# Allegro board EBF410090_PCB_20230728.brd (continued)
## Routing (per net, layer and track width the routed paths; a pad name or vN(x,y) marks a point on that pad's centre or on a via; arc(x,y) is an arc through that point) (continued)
VCC3V3_SD: length 145.4
  TOP w0.305: v1(17.73,30.2) 17.65,30.28 17.65,51.56 17.76,51.67 J30.244 17.78,54.09 17.78,58.93 18.01,59.16 J30.243
  ART03 w0.381: v1(109.65,25.41) 109.83,25.6 109.83,28.24 109.45,28.62 85.17,28.62 83.85,29.95 74.14,29.95 72.19,27.99 18.49,27.99 17.73,28.75 v1(17.73,30.2)
  BOTTOM w0.305: C54.1 114.42,26.39 ; 114.42,26.39 114.42,26.28 113.56,25.42 109.66,25.42 v1(109.65,25.41) ; 114.42,26.39 115.08,25.73 116.38,25.73 116.96,26.31 116.96,26.39 ; C73.1 116.96,26.39 ; 116.96,26.39 117.57,25.78 118.89,25.78 119.5,26.38 C74.1 120.35,25.56 J9.4
VCC3V3_SYS: length 11.2
  TOP w0.305: U31.5 v1(120.83,66.49) ; U32.5 v1(120.83,44.39)
  ART04 w0.305: v1(12.69,31.2) 12.7,31.2
  BOTTOM w0.305: U35.5 v1(71.56,26.52) ; R4.1 C8.1 7.23,50.43 7.7,49.96 7.7,47.92 C15.1
  vias: v1(5.46,45.85) v1(6.48,45.85) v1(7.49,45.85) v1(11.69,35.01) v1(11.69,31.2) v1(12.69,35.01) v1(70.56,26.52) v1(119.83,66.49) v1(119.83,44.39)
VCC5V0_SYS: length 16.2
  TOP w0.305: U33.5 v1(120.83,58.36) ; v1(13.26,52.32) 12.13,53.46 8.2,53.46 8.07,53.33 R16.1 ; U34.5 v1(120.83,36.26) ; U29.5 v1(120.83,61.66) ; U30.5 v1(120.83,39.56)
  ART04 w0.305: v1(120.83,61.66) v1(120.83,58.36)
  BOTTOM w0.305: C51.1 14.11,53.74 C20.1 R11.1
  vias: v1(13.26,51.32) v1(13.26,50.32) v1(14.26,52.32) v1(14.26,51.32) v1(14.26,50.32) v1(19.92,52.58) v1(19.89,51.69) v1(119.83,61.66) v1(119.83,58.36) v1(119.83,39.56) v1(119.83,36.26)
VCC5V0_SYS_2: length 16
  ART04 w0.508: v1(121.79,85.66) v1(121.79,84.41)
  BOTTOM w0.305: U21.5 v1(121.79,85.66) ; C36.1 13.85,69.05 13.26,69.65 7.7,69.65 7.37,69.97 C29.1 R20.1
  BOTTOM w0.381: R10.1 25.91,61.18 v1(25.51,60.78)
  vias: v1(11.69,38.82) v1(12.69,38.82) v1(15.38,69.23) v1(15.38,68.23) v1(16.38,69.29) v1(16.38,68.23) v1(106.92,84.71) v1(107.92,84.71)
VCC5V0_USB20_HOST: length 15.2
  BOTTOM w0.508: J17.1 J17.7 116.15,82.35 115.57,82.93 C113.1 C112.1 C117.1 C116.1 118.68,85.66 U21.1
VCC5V0_USB30_HOST: length 18.8
  TOP w0.508: J15.10 97.62,77.17 98.81,78.36 98.81,79.71 98.14,80.37 J15.1
  BOTTOM w0.508: J15.1 97.92,81.15 97.92,85.99 98.42,86.49 C123.1 C122.1 103.57,85.66 U24.1
VCC_1V8: length 109.1
  TOP w0.305: J30.245 17.51,59.55 17.26,59.3 J30.246 17.26,52.19 17.02,51.94 v1(17.02,38.48)
  ART04 w0.381: v1(33.76,37.41) 48.95,37.41 50.29,36.07 62.43,36.07 63.09,36.73 77.98,36.73 78.98,37.73 78.98,45.6 v1(78.24,46.35)
  BOTTOM w0.203: R38.1 16.71,34.68 16.46,34.93 16.46,37.34 16.83,37.71 C52.1
  BOTTOM w0.305: v1(17.02,38.48) C52.1 C57.1 C58.1 20.88,37.71 U8.8 22.35,37.72 23.37,38.73 30.63,38.73 31.24,38.12 R37.1 33.46,36.19 33.76,36.49 v1(33.76,37.41) ; L7.2 77.47,48.17 C105.1 v1(78.24,46.35)
VCC_12V: length 23.9
  TOP w0.305: C165.1 R196.1 128.49,26.67 v1(128.74,26.93) ; v1(8.43,58.16) 8.26,57.99 R14.1 ; R23.1 v1(2.16,63.78) ; R7.1 7.24,59.89
  BOTTOM w0.305: C38.1 v1(21.58,43.73) R27.1 ; C22.1 v1(8.43,58.16)
  BOTTOM w0.381: v1(25.51,59.78) 27.51,59.78 27.81,60.09 27.81,60.96 27.43,61.34 R9.1
  BOTTOM w0.508: v1(128.74,26.93) 125.06,26.93 124.45,27.54 v1(124.45,31.7)
  vias: v1(1.84,61.01) v1(1.84,59.99) v1(2.85,61.01) v1(2.85,59.99) v1(9.09,63.01) v1(9.09,62.01) v1(9.09,61.01) v1(10.09,63.01) v1(10.09,62.01) v1(10.09,61.01) v1(16.26,44.94) v1(16.26,43.94) v1(97.52,41.25) v1(98.52,41.25) v1(99.52,41.25) v1(124.45,32.7)
VCC_RTC: length 26.8
  TOP w0.305: J30.248 16.76,59.74 17.01,59.99 J30.247 17.01,63.37 18.21,64.57 18.21,73.33 17.88,73.66 15.95,73.66 v1(15.64,73.97)
  BOTTOM w0.305: R51.2 15.33,75.32 15.64,75.01 v1(15.64,73.97)
VCCA_1V8: length 57.1
  TOP w0.305: J30.239 19.01,58.51 18.76,58.26 J30.240 18.76,52.15 19.1,51.81 19.1,41.27 v1(20.01,40.36) ; C53.1 v1(27.56,40.66) ; v1(5.69,41.63) 6.25,42.19 6.25,44.04 4.83,45.46 4.83,46.49 R239.2 ; R35.1 v1(27.56,44.16)
  ART03 w0.381: v1(5.69,41.63) 18.74,41.63 v1(20.01,40.36) 20.88,41.22 27,41.22 v1(27.56,40.66)
  BOTTOM w0.305: v1(27.56,40.66) 27,41.22 27,43.6 v1(27.56,44.16)
VCCIO_ACODEC: length 36.5
  TOP w0.305: R215.1 36.2,66.67 C186.1 v1(36.2,68.96) ; J30.242 18.26,58.57 18.51,58.82 J30.241 18.51,63.72 19.05,64.26 19.05,66.17 19.94,67.05 19.94,68.53 20.24,68.83 31.89,68.83 v1(32.51,68.21)
  BOTTOM w0.254: 32.51,68.97 v1(32.51,68.21)
  BOTTOM w0.305: v1(36.2,68.96) 35.05,70.11 R217.1 C191.1 32.51,68.97 C55.1
VDD_3V3: length 101.3
  TOP w0.305: LED3.2 LED2.2 LED1.2 ; Q7.2 91.94,33.24 C109.1 R127.1 91.95,31.35 92.61,30.7 92.61,28.11 v1(92.91,27.81) ; v1(125.43,68.83) R168.1 R164.1 ; v1(125.43,46.73) R170.1 R166.1
  TOP w0.381: LED1.2 v1(128.65,14.47)
  TOP w0.762: C431.1 88.01,12.66 J34.1
  PWR05 w0.508: 112.01,9.94 J36.1 ; J36.1 111.28,10.67 ; J36.1 112.74,10.67 ; J36.1 112.01,11.4 ; J35.1 100.74,10.67 ; J35.1 99.28,10.67 ; J35.1 100.01,11.4 ; J35.1 100.01,9.94 ; J34.1 88.01,11.4 ; J34.1 88.74,10.67 ; J34.1 88.01,9.94 ; J34.1 87.28,10.67 ; J32.1 76.01,11.4 ; J32.1 76.74,10.67 ; J32.1 75.28,10.67 ; J32.1 76.01,9.94
  BOTTOM w0.305: C5.1 7.74,31.88 C62.1 7.9,30.7 U10.5 ; v1(73.28,68.2) 72.76,68.71 R159.1 ; L5.2 73.44,35.69 C90.1 v1(74.42,34.92) 73.33,33.83 69.27,33.83 68.76,33.32 68.76,31.99 68.15,31.38 C75.1 U14.8 ; v1(54.23,31.38) C76.1 U15.8 ; v1(7.87,19.43) C59.1 9.45,18.66 9.76,18.96 9.76,19.74 9.45,20.04 U9.5 ; L6.2 56.23,38.23 C94.1 48.92,38.23 48.62,37.93 48.62,32.45 49.23,31.84 49.69,31.84 v1(49.69,31.85) 49.69,31.84 D20.2 ; v1(83.31,68.2) 83.31,68.32 R156.1 ; R39.1 v1(6.48,16.89) ; U13.16 40.25,31.37 C69.1 v1(41.01,31.38) ; R69.1 v1(68.51,20.71) ; R44.1 v1(127.76,11.17) ; 5.07,31.63 4.94,31.51 R42.1 ; C6.1 v1(5.69,32.01) ; v1(29.08,32.38) R52.1 R53.1 R55.1 R54.1 ; v1(128.65,79.12) C127.1 127.75,80.11 R152.1 ; R70.1 v1(54.36,20.71) ; R68.1 v1(48.82,20.71) ; D19.2 v1(63.78,31.88) ; D6.2 14.33,74.13 14.64,73.82 v1(14.64,72.97) ; R157.1 77.72,68.71 v1(78.23,68.2) ; R67.1 v1(62.87,20.71)
  BOTTOM w0.381: R47.2 v1(122.05,13.21)
  vias: v1(4.69,32.01) v1(14.64,71.97)
VDD_5V: length 33.8
  TOP w0.305: Q9.1 84.18,68.38 84.18,66.5 83.74,66.06 79.02,66.06 77.95,65 70.43,65 69.47,64.03 59.49,64.03 D27.2
  ART03 w0.305: v1(19.88,47.1) v1(19.88,48.1) ; v1(33.86,41.13) v1(33.86,42.13)
  ART04 w0.305: v1(33.86,41.13) v1(33.86,42.13)
  vias: v1(55.47,69.2) v1(56.47,69.2)
B_DM1: length 27.1
  BOTTOM w0.158: J15.11 93.91,77.17 92.82,76.07 92.82,75.04 91.76,73.98 85.78,73.98 84.6,75.16 84.6,77.08 84.96,77.44 84.96,78.1 85.83,78.97 86.67,78.97 90.76,83.07 90.76,83.84 90.69,83.91 U18.5 U18.6 90.69,85.97 R130.1
B_DM2: length 7.8
  BOTTOM w0.158: J17.8 112.83,79.31 112.83,80.97 112.08,81.72 112.08,82.44 112.15,82.51 U20.4 U20.7 112.15,85.6 R139.1
B_DM3: length 13
  BOTTOM w0.158: J17.2 112.83,76.31 112.83,76.53 113.01,76.71 114.25,76.71 115.09,77.55 115.09,80.62 113.58,82.13 113.58,82.44 113.65,82.51 U20.1 U20.10 113.65,85.08 R132.1
B_DP1: length 26.2
  BOTTOM w0.158: J15.12 92.46,76.99 92.46,75.19 91.61,74.34 91.16,74.34 arc(91.03,74.4) 90.98,74.52 arc(90.93,74.65) 90.8,74.7 90.53,74.7 arc(90.4,74.65) 90.35,74.52 arc(90.3,74.4) 90.17,74.34 89.89,74.34 arc(89.77,74.4) 89.72,74.52 arc(89.66,74.65) 89.54,74.7 89.26,74.7 arc(89.14,74.65) 89.08,74.52 arc(89.03,74.4) 88.91,74.34 88.63,74.34 arc(88.5,74.4) 88.45,74.52 arc(88.4,74.65) 88.27,74.7 87.99,74.7 arc(87.87,74.65) 87.82,74.52 arc(87.77,74.4) 87.64,74.34 87.36,74.34 arc(87.24,74.4) 87.18,74.52 arc(87.13,74.65) 87.01,74.7 86.73,74.7 arc(86.6,74.65) 86.55,74.52 arc(86.5,74.4) 86.37,74.34 85.93,74.34 84.96,75.31 84.96,76.93 85.32,77.29 85.32,77.95 85.98,78.61 86.82,78.61 91.12,82.92 91.12,83.84 91.19,83.91 U18.4 U18.7 91.19,85.24 R131.1
B_DP2: length 8
  BOTTOM w0.158: J17.9 112.47,79.31 112.47,80.82 111.72,81.57 111.72,82.44 111.65,82.51 U20.5 U20.6 111.65,85.08 R140.1
B_DP3: length 12.8
  BOTTOM w0.158: R133.1 113.15,85.6 U20.9 U20.2 113.15,82.51 113.22,82.44 113.22,81.98 114.73,80.47 114.73,77.7 114.1,77.07 112.86,77.07 112.47,76.68 112.47,76.31 J17.3
BD_CH3: length 9.2
  TOP w0.156: J30.204 27.76,50.87 C56.1 28.12,50.11 28.12,48.81 R36.1 28.12,47.69 28.12,46.4 R35.2
CAM0_NRST: length 72.8
  TOP w0.156: J30.25 74.51,60.78
  TOP w0.305: 74.51,60.78 v1(74.51,60.78)
  BOTTOM w0.156: J20.22 123.7,78.16 123.11,78.74 117.73,78.74 117.22,78.23 117.22,74.8 116.59,74.17 108.2,74.17 107.57,73.53 103.76,73.53 103.25,74.04 93.85,74.04 90.81,70.99 85.85,70.99 85.47,70.61 85.47,66.22 85.16,65.91 75.06,65.91 74.51,65.37 v1(74.51,60.78)
CAM0_PWDN: length 104.1
  TOP w0.156: v1(78.24,43.35) 77.76,43.83 77.04,43.83 76.2,44.67 76.2,48.51 74.26,50.45 J30.26
  ART03 w0.142: v1(78.24,43.35) 79.14,43.35 80.19,44.4 87.96,44.4 89.81,46.25 114.43,46.25 116.13,47.95 119.34,47.95 v1(119.83,47.46)
  ART04 w0.142: v1(135.55,68.24) 135.55,69.39 135.26,69.67 129.98,69.67 129.69,69.39 129.69,59.64 129.41,59.36 127.03,59.36 126.75,59.07 126.75,49.33 125.86,48.44 122.28,48.44 121.3,47.46 v1(119.83,47.46)
  BOTTOM w0.156: J20.15 131.8,74.65 132.23,74.22 133.4,74.22 133.65,73.96 133.65,70.31 135.55,68.42 v1(135.55,68.24)
CAM0_PWR_EN: length 137.4
  TOP w0.156: v1(86.23,33.07) 86.39,33.22 86.39,50.01 84.71,51.69 79.76,51.69 79.26,52.18 J30.6 ; R180.1 v1(116.75,59.24)
  ART03 w0.142: v1(127.45,34.7) 127.3,34.55 127.3,24.64 127.56,24.38 129.63,24.38 129.92,24.09 129.92,18.29 129.21,17.58 122.53,17.58 122.17,17.93 122.17,21.03 119.89,23.32 113.47,23.32 113.18,23.6 113.18,31.98 112.85,32.31 94.44,32.31 93.88,32.87 86.43,32.87 v1(86.23,33.07)
  BOTTOM w0.156: v1(127.45,34.7) 126.57,35.58 126.57,49.73 125.96,50.34 117.53,50.34 117.13,50.73 117.13,58.86 v1(116.75,59.24)
CAM1_NRST: length 90.6
  TOP w0.156: J30.23 75.01,60.28 v1(75.51,59.78)
  BOTTOM w0.156: J21.22 128.65,61.39 128.41,61.15 128.41,57.69 128.13,57.41 120.85,57.41 120.32,57.94 120.32,62.45 120.48,62.61 121.21,62.61 121.44,62.84 121.44,68.02 119.81,69.65 119.81,72.58 119.5,72.9 116.79,72.9 116.1,73.58 109.07,73.58 107.75,72.26 103.76,72.26 102.49,73.53 94.23,73.53 91.06,70.36 86.42,70.36 86.11,70.04 86.11,65.72 85.79,65.4 75.56,65.4 75.03,64.87 75.03,60.27 v1(75.51,59.78)
CAM1_PWDN: length 77.4
  TOP w0.156: J30.16 76.76,51.51 78.61,49.66 83.51,49.66 84.27,48.89 84.27,42.47 v1(84.22,42.42)
  ART03 w0.142: v1(84.22,42.42) 88.65,42.42 89.66,43.43 114.33,43.43 115.04,44.14 116.03,44.14 116.23,44.35 116.23,45.36 116.74,45.87 119.24,45.87 v1(119.83,46.46)
  ART04 w0.142: v1(119.83,46.46) 122.13,46.46 122.91,47.24 126.62,47.24 127.3,47.93 127.3,58.18 127.59,58.46 128.35,58.46 v1(128.93,57.89)
  BOTTOM w0.156: J21.15 v1(128.93,57.89)
CAM1_PWR_EN: length 73.1
  TOP w0.156: R187.1 117.73,36.77 117.73,34.88 117.42,34.57 112.2,34.57 111.89,34.88 111.89,36.3 111.61,36.57 110.32,36.57 v1(109.73,37.16) ; J30.49 68.51,60.78
  TOP w0.305: 68.51,60.78 v1(68.51,60.78)
  ART03 w0.142: v1(109.73,37.16) 87.22,37.16 85.29,39.09 v1(83.57,39.09)
  BOTTOM w0.156: v1(68.51,60.78) 68.51,60.47 69,59.98 69,58.76 73.81,53.95 81.05,53.95 82.09,52.91 82.09,49.99 83.44,48.64 83.44,39.22 v1(83.57,39.09)
CC1: length 5.1
  TOP w0.156: v1(28,80.82) 28.58,81.4 J16.A5
  BOTTOM w0.156: D26.2 v1(28,80.82)
CC2: length 5.1
  TOP w0.156: v1(26.1,80.82) 25.58,81.34 J16.B5
  BOTTOM w0.156: D26.1 v1(26.1,80.82)
CSI_RX_D2N_S0: length 9.5
  BOTTOM w0.124: R179.2 123.06,73.47 123.41,73.81 123.41,75.15 123.83,75.57 129.51,75.57 129.6,75.65 J20.17
CSI_RX_D2N_S1: length 32.2
  ART03 w0.113: v1(123.83,64.34) 124.14,64.03 124.14,57.79 124.77,57.16 129.61,57.16 129.91,57.46 129.91,61.65 130.1,61.84 130.71,61.84 130.9,61.65 130.9,57.81 131.81,56.89 131.82,56.89 131.82,56.73 v1(131.47,56.39)
  BOTTOM w0.124: R181.2 123.06,70.55 123.41,70.2 123.41,69.55 124.13,68.82 124.13,64.64 v1(123.83,64.34) ; J21.12 v1(131.47,56.39)
CSI_RX_D2P_S0: length 10.4
  BOTTOM w0.124: J20.16 129.6,75.16 129.51,75.24 128.18,75.24 arc(128.07,75.2) 128.02,75.09 arc(127.98,74.97) 127.86,74.93 127.68,74.93 arc(127.57,74.97) 127.53,75.09 arc(127.48,75.2) 127.37,75.24 127.19,75.24 arc(127.07,75.2) 127.03,75.09 arc(126.98,74.97) 126.87,74.93 126.69,74.93 arc(126.58,74.97) 126.53,75.09 arc(126.49,75.2) 126.38,75.24 126.19,75.24 arc(126.08,75.2) 126.04,75.09 arc(125.99,74.97) 125.88,74.93 125.7,74.93 arc(125.59,74.97) 125.54,75.09 arc(125.5,75.2) 125.39,75.24 125.2,75.24 arc(125.09,75.2) 125.05,75.09 arc(125,74.97) 124.89,74.93 124.71,74.93 arc(124.6,74.97) 124.55,75.09 arc(124.5,75.2) 124.39,75.24 123.97,75.24 123.73,75.01 123.73,73.81 124.08,73.47 R177.2
CSI_RX_D2P_S1: length 33.4
  ART03 w0.113: v1(132.47,56.39) 132.13,56.73 132.13,57.02 131.95,57.21 131.94,57.21 131.22,57.94 131.22,61.78 130.84,62.15 129.96,62.15 129.59,61.78 129.59,57.59 129.48,57.47 124.9,57.47 124.45,57.92 124.45,64.03 v1(124.76,64.34)
  BOTTOM w0.124: v1(132.47,56.39) 131.97,55.89 J21.11 ; R178.2 124.08,70.55 123.73,70.2 123.73,69.69 124.46,68.96 124.46,64.64 v1(124.76,64.34)
CSI_RX_D3N_S0: length 13
  BOTTOM w0.124: R185.2 121.03,73.47 121.38,73.81 121.38,76.63 121.82,77.07 129.51,77.07 129.6,77.16 J20.20
CSI_RX_D3N_S1: length 35.6
  ART03 w0.113: v1(121.47,59.51) 121.78,59.21 121.78,54.81 122.13,54.46 122.64,54.46 122.95,54.77 122.95,55.56 123.08,55.69 123.27,55.69 123.4,55.56 123.4,54.77 123.72,54.46 124.17,54.46 124.49,54.77 124.49,55.56 124.62,55.69 124.81,55.69 124.94,55.56 124.94,54.77 125.25,54.46 125.7,54.46 126.02,54.77 126.02,55.56 126.15,55.69 126.34,55.69 126.47,55.56 126.47,54.77 126.79,54.46 129.62,54.46 130.44,55.28 131.7,55.28 131.82,55.17 131.82,54.73 v1(131.47,54.39)
  BOTTOM w0.124: J21.8 v1(131.47,54.39) ; v1(121.47,59.51) 121.77,59.81 121.77,61.04 122.33,61.6 122.33,68.39 121.38,69.35 121.38,70.2 121.03,70.55 R186.2
CSI_RX_D3P_S0: length 13.4
  BOTTOM w0.124: R183.2 122.05,73.47 121.7,73.81 121.7,76.49 121.95,76.74 124.65,76.74 arc(124.74,76.7) 124.78,76.61 arc(124.82,76.52) 124.91,76.48 125.14,76.48 arc(125.24,76.52) 125.28,76.61 arc(125.31,76.7) 125.41,76.74 125.64,76.74 arc(125.73,76.7) 125.77,76.61 arc(125.81,76.52) 125.9,76.48 126.14,76.48 arc(126.23,76.52) 126.27,76.61 arc(126.31,76.7) 126.4,76.74 126.63,76.74 arc(126.72,76.7) 126.76,76.61 arc(126.8,76.52) 126.89,76.48 127.13,76.48 arc(127.22,76.52) 127.26,76.61 arc(127.3,76.7) 127.39,76.74 129.51,76.74 129.6,76.65 J20.19
CSI_RX_D3P_S1: length 36.8
  ART03 w0.113: v1(122.4,59.51) 122.09,59.21 122.09,54.94 122.26,54.77 122.5,54.77 122.64,54.9 122.64,55.69 122.95,56.01 123.4,56.01 123.72,55.69 123.72,54.9 123.85,54.77 124.04,54.77 124.17,54.9 124.17,55.69 124.49,56.01 124.94,56.01 125.25,55.69 125.25,54.9 125.39,54.77 125.57,54.77 125.7,54.9 125.7,55.69 126.02,56.01 126.47,56.01 126.79,55.69 126.79,54.9 126.92,54.77 129.49,54.77 130.31,55.6 131.83,55.6 132.13,55.3 132.13,54.73 v1(132.47,54.39)
  BOTTOM w0.124: v1(132.47,54.39) 131.97,53.89 J21.7 ; R184.2 122.05,70.55 121.7,70.2 121.7,69.48 122.66,68.53 122.66,61.47 122.1,60.91 122.1,59.81 v1(122.4,59.51)
CTP0_INT: length 90.8
  TOP w0.156: J30.30 73.26,50.05 74.55,48.77 74.55,44.25 75.97,42.83 77.76,42.83 v1(78.24,42.35) ; J18.11 128.64,69.12 v1(127.91,69.85) R163.2
  ART03 w0.142: v1(78.24,42.35) 79.81,42.35 81,43.53 88.37,43.53 89.28,44.45 114.02,44.45 116.43,46.86 118.23,46.86 v1(118.83,47.46)
  ART04 w0.142: v1(118.83,47.46) 119.37,48 121.21,48 122.81,49.61 125.5,49.61 126.29,50.39 126.29,60.06 126.57,60.35 128.19,60.35 128.37,60.53 128.37,69.39 v1(127.91,69.85)
CTP0_RST: length 106.6
  TOP w0.156: J18.12 131.35,69.62 131.37,69.64 132.22,69.64 132.55,69.31 v1(132.55,68.24) ; J30.34 72.26,50.16 74.04,48.39 v1(74.04,43.43)
  ART03 w0.142: v1(134.63,52.39) 134.13,51.89 122.71,51.89 120.93,50.11 115.62,50.11 113.39,47.88 102.95,47.88 102.01,48.82 89.71,48.82 87.76,46.86 77.04,46.86 76.58,46.4 76.58,43.79 76.23,43.43 v1(74.04,43.43)
  ART04 w0.142: v1(134.63,52.39) 134.72,52.48 134.72,65.23 132.99,66.95 132.99,67.79 v1(132.55,68.24)
  BOTTOM w0.156: R167.2 127.44,65.78 127.13,66.1 127.13,66.74 127.44,67.05 127.72,67.05 127.72,67.05 131.19,67.05 131.44,67.31 131.44,67.94 131.74,68.24 v1(132.55,68.24)
CTP1_INT: length 79.5
  TOP w0.156: R165.2 124.35,48.23 v1(124.35,47.95) 124.48,47.83 124.96,47.35 128.01,47.35 128.34,47.03 J19.11 ; J30.33 72.51,60.78
  TOP w0.305: 72.51,60.78 v1(72.51,60.78)
  ART03 w0.142: v1(124.35,47.95) 123.67,47.28 123.67,44.32 122.02,42.67 90.3,42.67 v1(89.66,42.04)
  BOTTOM w0.156: v1(89.66,42.04) 89.66,50.36 89.35,50.67 86.23,50.67 84.71,52.2 84.71,54.42 82.69,56.44 75.74,56.44 73.03,59.15 73.03,60.27 v1(72.51,60.78)
CTP1_RST: length 83.9
  TOP w0.156: J19.12 128.6,47.53 128.24,47.88 v1(127.91,47.88) R169.2 ; J30.31 73.01,60.28 v1(73.51,59.78)
  ART03 w0.142: v1(127.91,47.88) 129.18,47.88 129.46,47.59 129.46,42.47 129.21,42.21 123.8,42.21 123.37,41.78 91.44,41.78 v1(90.68,41.02)
  BOTTOM w0.156: v1(73.51,59.78) 73.51,59.35 76.02,56.84 82.85,56.84 85.12,54.58 85.12,52.42 86.42,51.12 90.23,51.12 90.68,50.67 v1(90.68,41.02)
DBG_RX: length 1.7
  BOTTOM w0.156: R41.2 7.25,26.14 U10.2
DBG_RXD: length 4.5
  BOTTOM w0.156: R41.1 Z3.1 3.09,24.89 J6.3
DBG_TX: length 4.4
  BOTTOM w0.156: R40.2 9.62,22.48 9.78,22.32 9.78,21.5 9.62,21.34 U9.4
DBG_TXD: length 4.9
  BOTTOM w0.156: J6.2 4.15,23.49 Z2.1 R40.1
DM4: length 4.1
  TOP w0.158: J24.36 98.8,61.91 98.58,61.69 98.58,60.56 D35.2 98.93,60.19 R213.1
DP4: length 4.1
  TOP w0.158: R214.1 97.92,60.19 D36.2 98.22,60.51 98.22,61.69 98,61.91 J24.38
DSI0_RST: length 96.9
  TOP w0.156: J30.24 74.76,50.71 76.71,48.77 76.71,44.88 v1(77.24,44.35) ; v1(133.55,67.24) 134.04,67.74 134.04,69.93 132.85,71.12 J18.15
  ART03 w0.142: v1(134.63,51.39) 134.54,51.48 122.84,51.48 121.09,49.73 115.87,49.73 113.64,47.5 102.44,47.5 101.55,48.39 89.92,48.39 87.45,45.92 77.42,45.92 77.24,45.74 v1(77.24,44.35)
  ART04 w0.142: v1(133.55,67.24) 135.13,65.66 135.13,51.89 v1(134.63,51.39)
DSI0_TE: length 92.3
  TOP w0.156: J30.22 75.26,50.85 77.22,48.89 77.22,45.37 v1(78.24,44.35)
  ART03 w0.142: v1(78.24,44.35) 79.28,45.39 87.55,45.39 90.08,47.92 101.41,47.92 102.23,47.09 113.97,47.09 116.13,49.25 121.51,49.25 122.78,50.52 134.5,50.52 v1(134.63,50.39)
  ART04 w0.142: v1(134.63,50.39) 134.11,50.91 134.11,53.54 133.71,53.95 128.22,53.95 127.93,54.24 v1(127.93,57.89)
  BOTTOM w0.156: v1(127.93,57.89) 127.44,57.89 127.13,58.2 127.13,64.46 127.44,64.77 R161.1
DSI1_RST: length 84.7
  TOP w0.156: J19.15 v1(131.57,49.03) ; v1(72.51,59.78) 72.01,60.28 J30.35
  ART03 w0.142: v1(131.57,49.03) 130.59,50.01 125.3,50.01 124.89,49.61 124.89,44.19 122.99,42.29 90.93,42.29 v1(89.66,41.02)
  BOTTOM w0.156: v1(72.51,59.78) 72.51,58.83 75.31,56.03 82.52,56.03 84.3,54.25 84.3,51.84 86.11,50.04 87.95,50.04 88.27,49.72 88.27,42.42 v1(89.66,41.02)
DSI1_TE: length 88.6
  TOP w0.156: J30.37 71.51,60.78 ; R162.1 v1(125.43,49.02)
  TOP w0.305: 71.51,60.78 v1(71.51,60.78)
  ART03 w0.142: v1(89.66,40.13) 90.81,40.13 91.44,40.77 123.52,40.77 123.88,41.12 129.62,41.12 130.07,41.58 130.07,48.74 129.79,49.02 v1(125.43,49.02)
  BOTTOM w0.156: v1(71.51,60.78) 72,60.3 72,58.61 74.96,55.65 82.14,55.65 83.92,53.87 83.92,51.33 85.72,49.53 87.44,49.53 87.76,49.22 87.76,42.04 v1(89.66,40.13)
EDP_AUXN: length 4
  TOP w0.124: R192.2 C157.2 127.49,24.34 129.06,24.34 129.14,24.43 J22.10
EDP_AUXP: length 4
  TOP w0.124: R189.2 C156.2 127.59,24.01 129.06,24.01 129.14,23.93 J22.9
EDP_BL_EN: length 137.7
  TOP w0.156: v1(46.69,31.1) 46.76,31.17 J30.136 ; J22.22 v1(128.74,30.43)
  ART03 w0.142: v1(46.69,31.1) 47.16,31.57 48.79,31.57 49.42,30.95 84.42,30.95 85.57,29.79 110.26,29.79 110.97,29.08 110.97,22.43 111.51,21.89 119.74,21.89 121.26,20.37 121.26,17.22 121.74,16.74 131.55,16.74 132.11,17.3 132.11,25.88 131.7,26.29 129.62,26.29 129.34,26.57 129.34,29.83 v1(128.74,30.43)
EDP_BL_PWM: length 168.6
  TOP w0.156: v1(42.26,50.58) v1(42.26,13.71) ; J22.23 v1(131.61,30.93) ; v1(37.51,59.78) 37.01,60.28 J30.167
  ART03 w0.142: v1(37.51,59.78) 37.51,57.97 37.85,57.63 42.52,57.63 43.26,56.89 43.26,51.58 v1(42.26,50.58) ; v1(131.61,30.93) 130.71,30.93 130.43,30.64 130.43,27.2 130.71,26.92 133.84,26.92 134.26,26.5 134.26,17.42 133.1,16.25 130.45,16.25 129.82,15.62 120.14,15.62 118.24,13.71 95,13.71 94.49,14.22 84.45,14.22 83.9,13.67 73.2,13.67 72.26,14.6 43.15,14.6 v1(42.26,13.71)
EDP_HPDIN_M0: length 126.1
  TOP w0.156: J30.45 69.51,60.78 ; v1(132.61,27.43) 132.11,27.93 J22.17
  TOP w0.305: 69.51,60.78 v1(69.51,60.78)
  ART03 w0.142: v1(85.22,13.71) 94.23,13.71 94.74,13.21 118.49,13.21 120.4,15.11 130.05,15.11 130.61,15.67 133.3,15.67 134.72,17.09 134.72,27.13 134.43,27.43 v1(132.61,27.43)
  BOTTOM w0.156: v1(85.22,13.71) 84.18,14.75 84.18,35.41 84.71,35.94 84.71,48.26 82.58,50.39 82.58,53.06 81.28,54.35 74.17,54.35 70,58.53 70,60.3 v1(69.51,60.78)
EDP_PWR_EN: length 88.3
  TOP w0.156: J30.8 78.76,52.05 79.63,51.18 84.58,51.18 85.98,49.78 85.98,34.34 84.66,33.02 84.66,32.21 v1(84.71,32.16) ; v1(112.27,24.41) 114,24.41 114.45,24.87 114.45,26.59 114.83,26.97 117.86,26.97 118.29,26.54 R198.1
  ART03 w0.142: v1(112.27,24.41) 111.81,24.88 111.81,31.01 111.38,31.44 94.31,31.44 93.78,30.91 85.95,30.91 v1(84.71,32.16) 83.41,32.16 82.42,33.15 v1(70.61,33.15)
  BOTTOM w0.156: R193.1 v1(70.61,33.15)
EDP_TP_INT: length 75.3
  TOP w0.156: R190.2 64.52,13.17 J23.2 ; v1(82.87,14.22) 82.87,34.03 85.09,36.25 85.09,49.4 84.07,50.42 79.12,50.42 77.76,51.78 J30.12
  BOTTOM w0.156: J23.2 64.17,12.83 77.85,12.83 80.01,14.98 82.11,14.98 v1(82.87,14.22)
EDP_TP_RESET: length 71.3
  TOP w0.156: J30.14 77.26,51.64 78.87,50.04 83.82,50.04 84.71,49.15 84.71,36.57 82.37,34.24 82.37,15.19 v1(81.41,14.22) ; R191.2 65.53,12.19 J23.3
  BOTTOM w0.156: J23.3 65.54,12.19 78.36,12.19 80.39,14.22 v1(81.41,14.22)
EDP_TX_AUXN: length 149.9
  TOP w0.124: v1(27.48,59) 27.48,58.8 27.28,58.6 26.73,58.6 26.43,58.9 26.43,60.99 26.51,61.08 J30.209 ; C157.1 125.85,24.29 124.75,24.29 v1(124.45,24.59)
  ART03 w0.113: v1(27.48,59) 27.48,58.65 27.59,58.54 28.86,58.54 31.1,56.3 41.37,56.3 41.78,55.89 41.78,45.71 47.93,39.56 57.86,39.56 60.02,41.72 66.23,41.72 67.22,40.73 81.26,40.73 82.04,41.51 87.44,41.51 89.45,39.51 112.09,39.51 112.71,38.89 121.11,38.89 122.76,37.24 122.76,30.64 122.89,30.51 125.26,30.51 125.58,30.2 125.58,29.75 125.26,29.43 122.89,29.43 122.76,29.3 122.76,29.11 122.89,28.98 125.26,28.98 125.58,28.66 125.58,28.21 125.26,27.89 122.89,27.89 122.76,27.76 122.76,27.58 122.89,27.44 125.26,27.44 125.58,27.13 125.58,26.68 125.26,26.36 122.89,26.36 122.76,26.23 122.76,24.69 123.34,24.11 124.21,24.11 124.45,24.35 v1(124.45,24.59)
EDP_TX_AUXP: length 149.7
  TOP w0.124: C156.1 125.85,23.97 124.75,23.97 v1(124.45,23.67) ; v1(27.48,58.07) 27.28,58.27 26.59,58.27 26.1,58.76 26.1,60.99 26.01,61.08 J30.211
  ART03 w0.113: v1(27.48,58.07) 27.63,58.22 28.73,58.22 30.97,55.98 41.24,55.98 41.47,55.76 41.47,45.58 47.8,39.24 57.99,39.24 60.15,41.4 66.1,41.4 67.09,40.42 81.39,40.42 82.17,41.2 87.31,41.2 89.32,39.19 111.96,39.19 112.58,38.57 120.97,38.57 122.44,37.1 122.44,30.51 122.76,30.2 125.13,30.2 125.26,30.06 125.26,29.88 125.13,29.74 122.76,29.74 122.44,29.43 122.44,28.98 122.76,28.66 125.13,28.66 125.26,28.53 125.26,28.34 125.13,28.21 122.76,28.21 122.44,27.89 122.44,27.44 122.76,27.13 125.13,27.13 125.26,27 125.26,26.81 125.13,26.68 122.76,26.68 122.44,26.36 122.44,24.56 123.21,23.79 124.32,23.79 v1(124.45,23.67)
EDP_TX_D0N: length 148.7
  TOP w0.124: v1(24.89,56.66) 24.59,56.36 22.61,56.36 22.43,56.55 22.43,60.99 22.51,61.08 J30.225 ; v1(128.15,22.93) 128.65,22.43 J22.6
  ART03 w0.113: v1(24.89,56.66) 24.89,56.37 25,56.25 27.34,56.25 29.34,54.25 39.2,54.25 39.61,53.84 39.61,45.5 47.52,37.59 58.73,37.59 60.45,39.3 82.36,39.3 82.98,39.93 86.46,39.93 88.43,37.96 110.07,37.96 111.3,36.73 118.39,36.73 121.26,33.86 121.26,23.62 123.06,21.82 123.06,18.96 123.56,18.46 127.9,18.46 128.32,18.88 128.32,22.76 v1(128.15,22.93)
EDP_TX_D0P: length 148.6
  TOP w0.124: v1(24.89,55.73) 24.59,56.03 22.48,56.03 22.1,56.41 22.1,60.99 22.01,61.08 J30.227 ; J22.7 v1(128.95,22.93)
  ART03 w0.113: v1(24.89,55.73) 25.1,55.94 27.2,55.94 29.21,53.94 39.07,53.94 39.29,53.71 39.29,45.37 47.39,37.28 58.87,37.28 60.58,38.99 82.49,38.99 83.12,39.61 86.33,39.61 88.3,37.64 109.94,37.64 111.17,36.41 118.26,36.41 120.94,33.73 120.94,23.49 122.75,21.69 122.75,18.83 123.43,18.15 128.03,18.15 128.63,18.75 128.63,22.77 128.8,22.93 v1(128.95,22.93)
EDP_TX_D1N: length 150.8
  TOP w0.124: J22.3 129.14,20.93 129.06,21.01 124.76,21.01 v1(124.46,20.71) ; J30.221 23.51,61.08 23.43,60.99 23.43,57.81 23.71,57.53 25.84,57.53 v1(26.14,57.83)
  ART03 w0.113: v1(124.46,20.71) 124.77,21.02 125.27,21.02 125.49,20.79 125.49,19.49 125.27,19.26 124.03,19.26 123.8,19.5 123.8,22.42 122.03,24.18 122.03,36.51 120.9,37.64 112.6,37.64 111.49,38.75 89.02,38.75 87.05,40.72 82.56,40.72 81.86,40.02 66.66,40.02 65.83,40.85 60.41,40.85 58.1,38.54 47.82,38.54 41.01,45.35 41.01,54.84 40.6,55.26 39.33,55.26 arc(39.25,55.29) 39.22,55.36 arc(39.18,55.44) 39.11,55.47 38.87,55.47 arc(38.8,55.44) 38.77,55.36 arc(38.73,55.29) 38.66,55.26 38.42,55.26 arc(38.35,55.29) 38.31,55.36 arc(38.28,55.44) 38.21,55.47 37.97,55.47 arc(37.89,55.44) 37.86,55.36 arc(37.83,55.29) 37.75,55.26 37.52,55.26 arc(37.44,55.29) 37.41,55.36 arc(37.38,55.44) 37.3,55.47 37.07,55.47 arc(36.99,55.44) 36.96,55.36 arc(36.93,55.29) 36.85,55.26 36.62,55.26 arc(36.54,55.29) 36.51,55.36 arc(36.48,55.44) 36.4,55.47 36.17,55.47 arc(36.09,55.44) 36.06,55.36 arc(36.03,55.29) 35.95,55.26 35.72,55.26 arc(35.64,55.29) 35.61,55.36 arc(35.58,55.44) 35.5,55.47 35.27,55.47 arc(35.19,55.44) 35.16,55.36 arc(35.12,55.29) 35.05,55.26 34.81,55.26 arc(34.74,55.29) 34.71,55.36 arc(34.67,55.44) 34.6,55.47 34.36,55.47 arc(34.29,55.44) 34.25,55.36 arc(34.22,55.29) 34.15,55.26 33.91,55.26 arc(33.83,55.29) 33.8,55.36 arc(33.77,55.44) 33.69,55.47 33.46,55.47 arc(33.38,55.44) 33.35,55.36 arc(33.32,55.29) 33.24,55.26 33.01,55.26 arc(32.93,55.29) 32.9,55.36 arc(32.87,55.44) 32.79,55.47 32.56,55.47 arc(32.48,55.44) 32.45,55.36 arc(32.42,55.29) 32.34,55.26 32.11,55.26 arc(32.03,55.29) 32,55.36 arc(31.97,55.44) 31.89,55.47 31.66,55.47 arc(31.58,55.44) 31.55,55.36 arc(31.52,55.29) 31.44,55.26 31.21,55.26 arc(31.13,55.29) 31.1,55.36 arc(31.06,55.44) 30.99,55.47 30.75,55.47 arc(30.68,55.44) 30.65,55.36 arc(30.61,55.29) 30.54,55.26 30.1,55.26 27.99,57.37 26.25,57.37 26.14,57.48 v1(26.14,57.83)
EDP_TX_D1P: length 149.6
  TOP w0.124: v1(124.46,21.64) 124.76,21.34 129.06,21.34 129.14,21.43 J22.4 ; J30.223 23.01,61.08 23.1,60.99 23.1,57.67 23.57,57.2 25.84,57.2 v1(26.14,56.9)
  ART03 w0.113: v1(26.14,56.9) 26.29,57.05 27.86,57.05 29.97,54.94 40.47,54.94 40.69,54.71 40.69,45.22 47.69,38.23 58.23,38.23 60.54,40.54 65.69,40.54 66.53,39.7 81.99,39.7 82.69,40.4 86.92,40.4 88.89,38.43 111.36,38.43 112.47,37.33 120.77,37.33 121.72,36.38 121.72,24.05 123.48,22.29 123.48,19.36 123.9,18.95 125.4,18.95 125.81,19.36 125.81,20.92 125.4,21.33 124.77,21.33 v1(124.46,21.64)
EXT_PWR_EN: length 102.7
  TOP w0.156: v1(20.32,60.78) 20.83,60.78 21.01,60.97 J30.231 ; R24.1 v1(5.21,63.78)
  ART03 w0.142: v1(14.98,31.2) 14.98,29.98 14.69,29.69 4.5,29.69 4.01,30.18 4.01,57.35 4.76,58.1 4.76,63.34 v1(5.21,63.78)
  BOTTOM w0.156: v1(20.32,60.78) 19.3,59.77 R3.1 20.1,54.85 20.47,54.48 20.47,45.46 20.88,45.06 22.45,45.06 22.76,44.75 22.76,39.42 22.08,38.74 18.38,38.74 18.08,39.04 16.26,39.04 15.95,38.73 15.95,34.21 16.64,33.53 16.64,32.4 16.33,32.09 R1.1 v1(14.98,31.2) ; v1(5.21,63.78) 5.85,64.42 6.44,64.42 8.38,62.48 8.38,59.41 7.95,58.98 7.95,57.33 7.75,57.12 6.43,57.12 6.23,57.32 R19.1
FAN: length 10.6
  BOTTOM w0.156: C30.1 25.91,65.52
  BOTTOM w0.381: R12.1 22.42,65.98 Q1.2 22.42,67.27 22.71,67.56 25.2,67.56 25.92,66.84 C30.1 ; 25.91,65.52 R10.2 R9.2
FSPI_CLK: length 22.6
  TOP w0.156: J30.218 24.26,52.64 23.87,52.24 23.87,35.17 23.5,34.8 23,34.8 v1(22.35,35.45)
  BOTTOM w0.156: v1(22.35,35.45) 22.08,35.18 U8.6
FSPI_CS0N: length 19.4
  TOP w0.156: v1(26.35,37.45) 26.37,37.46 26.37,51.21 26.76,51.6 J30.208
  BOTTOM w0.156: U8.1 26.62,37.72 v1(26.35,37.45)
FSPI_D0: length 33.2
  TOP w0.156: v1(25.35,34.45) 25.87,34.96 25.87,51.41 26.26,51.81 J30.210
  BOTTOM w0.156: J5.2 19.3,31.49 19.05,31.75 19.05,33.6 19.36,33.91 U8.5 24.81,33.91 v1(25.35,34.45)
FSPI_D1: length 21.3
  TOP w0.156: v1(25.35,36.45) 25.37,36.46 25.37,51.62 25.76,52.01 J30.212
  BOTTOM w0.156: v1(25.35,36.45) U8.2
FSPI_D2: length 26
  TOP w0.156: J30.214 25.26,52.22 24.87,51.83 24.87,35.96 v1(24.35,35.45)
  BOTTOM w0.156: R37.2 31.23,35.18 U8.3 24.62,35.18 v1(24.35,35.45)
FSPI_D3: length 23.4
  TOP w0.156: J30.216 24.76,52.43 24.35,52.02 v1(24.35,36.45)
  BOTTOM w0.156: R38.2 19.82,36.45 U8.7 v1(24.35,36.45)
GMAC1_INT: length 57.3
  TOP w0.156: v1(70.51,59.78) 70.01,60.28 J30.43
  ART03 w0.142: v1(66.55,34.92) 67.06,35.43 74.63,35.43 75.01,35.05 v1(84.71,35.05)
  BOTTOM w0.156: v1(70.51,59.78) 70.51,58.67 74.42,54.76 81.53,54.76 83,53.29 83,50.73 85.34,48.39 85.34,35.69 v1(84.71,35.05) ; R112.1 v1(66.55,34.92)
GMAC1_MCLKINOUT_M1: length 16
  TOP w0.156: J30.58 66.26,51.43 65.96,51.13 65.96,47.17 65.61,46.81 63.69,46.81 63.38,46.5 63.38,43.18 R115.1 R113.1
GMAC1_MDC_M1: length 8.7
  TOP w0.156: J30.78 61.26,50.5 v1(62.1,49.66)
  BOTTOM w0.156: R108.2 62.23,49.78 v1(62.1,49.66) 61.59,49.15 61.59,48.39 61.87,48.12 U16.13
GMAC1_MDIO_M1: length 10.1
  TOP w0.156: v1(62.1,48.64) 62.59,49.12 62.59,50.19 61.76,51.01 J30.76
  BOTTOM w0.156: R109.2 62.76,50.07 62.76,49.55 62.1,48.89 v1(62.1,48.64) 62.27,48.48 U16.14
GMAC1_RSTN: length 49.2
  TOP w0.156: v1(40.51,59.78) 40.01,60.28 J30.155
  ART03 w0.142: v1(56.31,48.06) 54.61,46.35 48.51,46.35 47.73,47.14 47.73,61.26 47.32,61.67 40.34,61.67 39.98,61.31 39.98,60.32 v1(40.51,59.78)
  BOTTOM w0.156: v1(56.31,48.06) 56.9,48.65 C86.1 56.9,50.49 57.22,50.8 58.02,50.8 58.33,51.11 58.33,51.79 58.64,52.1 60.67,52.1 R119.2 R120.2 61.21,48.27 61.47,48 61.47,46.95 U16.12
GMAC1_RXCLK_M1: length 31.1
  TOP w0.156: J30.82 v1(60.26,52.58)
  ART04 w0.142: v1(70.1,43.31) 70.1,41.71 69.9,41.5 69.48,41.5 69.32,41.67 69.32,44.61 69.15,44.78 68.91,44.78 68.75,44.61 68.75,41.67 68.58,41.5 64.54,41.5 64.34,41.71 64.34,46.48 64.08,46.73 60.93,46.73 60.26,47.41 v1(60.26,52.58)
  BOTTOM w0.156: R101.1 v1(70.1,43.31) R95.2
GMAC1_RXD0_M1: length 32.2
  TOP w0.156: J30.86 v1(59.26,52.58)
  ART04 w0.142: v1(59.26,52.58) 59.26,56.49 59.99,57.22 67.49,57.22 68.55,56.16 68.55,46.06 68.74,45.88 71.54,45.88 71.68,45.73 71.68,45.48 71.54,45.34 v1(70.1,45.34)
  BOTTOM w0.156: R93.2 v1(70.1,45.34) R96.1
GMAC1_RXD1_M1: length 30
  TOP w0.156: J30.88 v1(58.76,55.55)
  ART04 w0.142: v1(70.1,46.35) 71.74,46.35 71.88,46.5 71.88,46.74 71.74,46.89 69.23,46.89 69.09,47.03 69.09,56.67 68.11,57.65 59.53,57.65 58.76,56.88 v1(58.76,55.55)
  BOTTOM w0.156: R94.2 v1(70.1,46.35) R97.1
GMAC1_RXD2_M1: length 29.7
  TOP w0.156: J30.90 v1(58.26,52.58)
  ART04 w0.142: v1(70.1,47.37) 69.55,47.92 69.55,56.99 68.47,58.08 58.97,58.08 58.26,57.37 v1(58.26,52.58)
  BOTTOM w0.156: R99.1 v1(70.1,47.37) R103.1
GMAC1_RXD3_M1: length 30.6
  TOP w0.156: J30.92 v1(57.76,55.55)
  ART04 w0.142: v1(57.76,55.55) 57.76,58.14 58.12,58.5 69.69,58.5 70.1,58.09 70.1,52.37 70.27,52.2 70.57,52.2 70.74,52.03 70.74,51.8 70.57,51.63 70.27,51.63 70.1,51.46 70.1,51.23 70.27,51.06 70.57,51.06 70.74,50.89 70.74,50.66 70.57,50.49 70.27,50.49 70.1,50.32 70.1,50.09 70.27,49.92 70.57,49.92 70.74,49.75 70.74,49.52 70.57,49.35 70.27,49.35 70.1,49.18 v1(70.1,48.39)
  BOTTOM w0.156: R100.1 v1(70.1,48.39) R104.1
GMAC1_RXDV_CRS_M1: length 32.5
  TOP w0.156: J30.84 v1(59.76,55.55)
  ART04 w0.142: v1(70.1,44.32) 71.1,44.32 71.32,44.1 71.32,41.26 71.1,41.05 63.73,41.05 63.35,41.43 63.35,46.05 63.17,46.23 60.6,46.23 59.76,47.07 v1(59.76,55.55)
  BOTTOM w0.156: R102.1 v1(70.1,44.32) R105.1
GMAC1_TXCLK_M1: length 29
  TOP w0.156: J30.64 v1(64.76,55.55)
  ART04 w0.142: v1(65.28,48.64) 65.28,42.42 65.74,41.96 67.57,41.96 68.12,42.51 68.12,54.99 67.56,55.55 v1(64.76,55.55)
  BOTTOM w0.156: v1(65.28,48.64) 65.28,48.13 64.67,47.52 U16.20
GMAC1_TXD0_M1: length 17.5
  TOP w0.156: J30.72 v1(62.76,55.55)
  ART04 w0.142: v1(64.26,48.64) 64.26,47.78 63.75,47.27 61.29,47.27 60.88,47.67 60.88,55.12 61.32,55.55 v1(62.76,55.55)
  BOTTOM w0.156: v1(64.26,48.64) 64.26,48.26 63.96,47.96 63.96,47.95 63.86,47.86 U16.18
GMAC1_TXD1_M1: length 28.3
  TOP w0.156: J30.70 v1(63.26,52.58)
  ART04 w0.142: v1(63.26,52.58) 63.26,53.02 63.12,53.16 62.23,53.16 62.03,53.36 62.03,54.43 62.23,54.63 62.57,54.63 62.74,54.47 62.74,53.79 62.91,53.62 63.14,53.62 63.31,53.79 63.31,54.47 63.48,54.63 63.71,54.63 63.88,54.47 63.88,53.79 64.05,53.62 64.28,53.62 64.45,53.79 64.45,54.72 64.62,54.89 64.85,54.89 65.02,54.72 65.02,53.79 65.19,53.62 65.42,53.62 65.59,53.79 65.59,54.72 65.76,54.89 65.99,54.89 66.16,54.72 66.16,53.79 66.33,53.62 66.56,53.62 66.73,53.79 66.73,54.72 66.9,54.89 67.17,54.89 67.31,54.75 67.31,53.29 67.16,53.14 64.89,53.14 64.74,52.99 64.74,50.14 v1(64.26,49.66)
  BOTTOM w0.156: v1(64.26,49.66) 63.73,49.12 63.73,48.36 63.46,48.1 U16.17
GMAC1_TXD2_M1: length 27.8
  TOP w0.156: J30.68 v1(63.76,55.55)
  ART04 w0.142: v1(63.25,48.64) 63.25,47.84 63.1,47.7 61.56,47.7 61.42,47.84 61.42,54.81 61.67,55.07 62.99,55.07 63.27,55.35 63.27,55.88 63.12,56.03 60.26,56.03 60.12,56.17 60.12,56.62 60.27,56.77 65.62,56.77 65.76,56.63 65.76,56.2 65.62,56.06 64.27,56.06 v1(63.76,55.55)
  BOTTOM w0.156: U16.16 63.06,48.46 v1(63.25,48.64)
GMAC1_TXD3_M1: length 26.8
  TOP w0.156: J30.66 64.26,52.48 64.75,51.99 64.75,47.86 64.43,47.55 60.36,47.55 60.05,47.86 60.05,51.61 60.22,51.79 60.61,51.79 60.79,51.61 60.79,48.31 60.95,48.16 63.45,48.16 63.73,48.44 63.73,49.17 v1(63.25,49.66)
  BOTTOM w0.156: U16.15 62.67,48.74 63.25,49.33 v1(63.25,49.66)
GMAC1_TXEN_M1: length 28.7
  TOP w0.156: J30.62 v1(65.26,52.58)
  ART04 w0.142: v1(65.26,52.58) 65.75,52.09 67.34,52.09 67.64,51.79 67.64,42.7 67.36,42.42 65.99,42.42 65.81,42.59 65.81,43.59 65.98,43.76 66.33,43.76 66.5,43.93 66.5,44.16 66.33,44.33 65.98,44.33 65.81,44.5 65.81,44.73 65.98,44.9 66.33,44.9 66.5,45.07 66.5,45.3 66.33,45.47 65.98,45.47 65.81,45.64 65.81,47.29 65.98,47.46 66.36,47.46 66.52,47.62 66.52,47.86 66.36,48.03 65.98,48.03 65.81,48.19 65.81,49.12 v1(65.28,49.66)
  BOTTOM w0.156: v1(65.28,49.66) 64.77,49.15 64.77,48.26 64.27,47.75 U16.19
GPIO2_B7: length 106
  TOP w0.156: J30.17 76.51,60.78 ; v1(119.86,19.66) 122.68,19.66 123.43,18.91 R48.2
  TOP w0.305: 76.51,60.78 v1(76.51,60.78)
  ART03 w0.142: v1(119.86,19.66) 119.25,19.05 119.25,16.55 117.4,14.7 v1(95.68,14.7)
  BOTTOM w0.156: v1(76.51,60.78) 76.51,62.67 76.83,62.99 80.52,62.99 81.41,63.88 86.74,63.88 87.88,65.02 94.19,65.02 94.99,64.23 94.99,29.19 95.68,28.5 v1(95.68,14.7)
GPIO2_C0: length 99.3
  TOP w0.156: v1(119.86,18.66) 120.12,18.91 R49.2 ; J30.39 71.01,60.28 v1(71.51,59.78)
  ART03 w0.142: v1(90.04,14.7) 94.9,14.7 95.38,14.22 117.83,14.22 119.86,16.25 v1(119.86,18.66)
  BOTTOM w0.156: v1(71.51,59.78) 71.51,58.36 74.7,55.17 81.79,55.17 83.49,53.47 83.49,51 85.98,48.51 85.98,35.18 84.71,33.91 84.71,32.84 85.19,32.36 85.19,31.95 84.71,31.47 84.71,28.5 85.19,28.01 85.19,20.47 85.57,20.09 85.57,15.01 85.89,14.7 v1(90.04,14.7)
HDMI_5V: length 24
  TOP w0.305: v1(66.4,71.25) 67.26,70.38 72.01,70.38 Q11.1 73.69,68.7 R160.1 74.55,69.93 74.96,70.33 77.74,70.33 78.04,70.03 Q10.1 78.65,68.7 R158.1
  BOTTOM w0.305: U26.18 61.96,71.75 63.68,71.75 64.19,71.25 v1(66.4,71.25)
  BOTTOM w0.508: 61.84,69.35 U26.18
  vias: v1(63.18,65.91) v1(63.18,64.91)
HDMI_TX0N_PORT: length 32.5
  TOP w0.124: U26.9 60.84,77.16 60.67,77.32 60.15,77.32 58.32,75.49 58.32,75.17 55.72,72.57 55.41,72.57 55.32,72.48 U28.4 U28.7 53.59,72.48 53.51,72.57 52.8,72.57 52.22,71.99 52.22,70.66 51.91,70.35 50.69,70.35 50.54,70.2 50.54,69.98 50.67,69.85 52.02,69.85 52.37,69.49 52.37,68.93 52.02,68.57 49.92,68.57 49.79,68.45 49.79,66.94 49.48,66.62 48.96,66.62 48.64,66.94 48.64,68.45 48.52,68.57 48.12,68.57 47.93,68.37 47.93,66.51 arc(47.96,66.43) 48.04,66.39 arc(48.13,66.36) 48.16,66.27 48.16,66.01 arc(48.13,65.93) 48.04,65.9 arc(47.96,65.86) 47.93,65.78 47.93,65.52 arc(47.96,65.44) 48.04,65.4 arc(48.13,65.37) 48.16,65.28 48.16,65.02 arc(48.13,64.94) 48.04,64.91 arc(47.96,64.87) 47.93,64.79 47.93,64.53 arc(47.96,64.44) 48.04,64.41 arc(48.13,64.38) 48.16,64.29 48.16,64.03 arc(48.13,63.95) 48.04,63.91 arc(47.96,63.88) 47.93,63.8 47.93,63.54 48.01,63.46 J30.131
HDMI_TX0P_PORT: length 32
  TOP w0.124: U26.7 60.5,77.65 60.02,77.65 57.99,75.62 57.99,75.3 55.59,72.9 55.41,72.9 55.32,72.98 U28.5 U28.6 53.59,72.98 53.51,72.9 52.67,72.9 51.9,72.12 51.9,70.8 51.77,70.68 50.56,70.68 50.22,70.34 50.22,69.84 50.53,69.53 51.88,69.53 52.05,69.36 52.05,69.06 51.88,68.9 49.78,68.9 49.47,68.58 49.47,67.07 49.34,66.95 49.09,66.95 48.97,67.07 48.97,68.58 48.66,68.9 47.99,68.9 47.6,68.51 47.6,63.54 47.51,63.46 J30.133
HDMI_TX1N_PORT: length 31.3
  TOP w0.124: J30.135 47.01,63.46 46.93,63.54 46.93,63.8 arc(46.96,63.87) 47.03,63.9 arc(47.11,63.94) 47.14,64.01 47.14,64.29 arc(47.11,64.37) 47.03,64.4 arc(46.96,64.43) 46.93,64.51 46.93,64.79 arc(46.96,64.86) 47.03,64.9 arc(47.11,64.93) 47.14,65 47.14,65.28 arc(47.11,65.36) 47.03,65.39 arc(46.96,65.42) 46.93,65.5 46.93,68.93 47.76,69.76 47.93,69.76 48.2,69.5 48.65,69.5 49.02,69.86 49.02,70.31 48.75,70.58 48.75,70.75 48.92,70.93 49.1,70.93 49.37,70.66 49.81,70.66 50.18,71.03 50.18,71.47 49.91,71.74 49.91,71.92 50.09,72.09 50.26,72.09 50.53,71.83 50.98,71.83 51.35,72.19 51.35,72.64 51.08,72.91 51.08,73.08 51.25,73.26 51.43,73.26 51.7,72.99 52.14,72.99 52.51,73.36 52.51,73.8 52.24,74.07 52.24,74.25 52.57,74.57 53.51,74.57 53.59,74.49 U27.10 U27.1 55.32,74.49 55.41,74.57 55.88,74.57 59.33,78.03 59.33,78.56 59.69,78.92 59.97,78.92 60.31,78.57 U26.6
HDMI_TX1P_PORT: length 31.4
  TOP w0.124: J30.137 46.51,63.46 46.6,63.54 46.6,69.07 47.62,70.09 48.07,70.09 48.34,69.82 48.51,69.82 48.69,70 48.69,70.17 48.42,70.44 48.42,70.89 48.79,71.26 49.23,71.26 49.5,70.99 49.68,70.99 49.85,71.16 49.85,71.34 49.59,71.61 49.59,72.05 49.95,72.42 50.4,72.42 50.67,72.15 50.84,72.15 51.02,72.33 51.02,72.5 50.75,72.77 50.75,73.22 51.12,73.59 51.56,73.59 51.83,73.32 52.01,73.32 52.18,73.49 52.18,73.67 51.92,73.94 51.92,74.38 52.43,74.9 53.51,74.9 53.59,74.99 U27.9 U27.2 55.32,74.99 55.41,74.9 55.75,74.9 59.01,78.16 59.01,78.7 59.55,79.24 59.97,79.24 60.45,79.73 U26.4
HDMI_TX2N_PORT: length 31.7
  TOP w0.124: U26.3 60.42,80.71 59.85,80.71 58.59,81.97 56.34,81.97 56.04,81.66 56.04,81.41 arc(56.07,81.34) 56.14,81.31 arc(56.21,81.28) 56.24,81.21 56.24,80.92 arc(56.21,80.85) 56.14,80.82 arc(56.07,80.79) 56.04,80.72 56.04,80.42 arc(56.07,80.35) 56.14,80.32 arc(56.21,80.29) 56.24,80.22 56.24,79.93 arc(56.21,79.86) 56.14,79.83 arc(56.07,79.8) 56.04,79.73 56.04,79.43 arc(56.07,79.36) 56.14,79.33 arc(56.21,79.3) 56.24,79.23 56.24,78.93 arc(56.21,78.86) 56.14,78.83 arc(56.07,78.81) 56.04,78.73 56.04,76.39 55.72,76.07 55.41,76.07 55.32,75.99 U27.4 U27.7 53.59,75.99 53.51,76.07 52.81,76.07 45.93,69.19 45.93,63.54 46.01,63.46 J30.139
HDMI_TX2P_PORT: length 31.6
  TOP w0.124: U26.1 60.42,81.04 59.98,81.04 58.72,82.29 56.2,82.29 55.71,81.8 55.71,76.53 55.59,76.4 55.41,76.4 55.32,76.49 U27.5 U27.6 53.59,76.49 53.51,76.4 52.67,76.4 45.6,69.33 45.6,63.54 45.51,63.46 J30.141
HDMI_TX_CEC_PORT: length 32.2
  TOP w0.156: Q9.3 80.58,67.27 79.96,66.65 78.36,66.65 77.5,65.78 69.57,65.78 D31.2 68.55,66.04 67.06,66.04 66.29,66.8 59.94,66.8 59.44,67.31 59.44,73.12 U26.13
HDMI_TX_HPD_PORT: length 13.6
  TOP w0.156: v1(69.98,67.94) D28.2 68.55,68.58 61.09,68.58 60.84,68.83 U26.19
  BOTTOM w0.156: R154.2 R155.1 69.85,67.82 v1(69.98,67.94)
HDMI_TX_HPDIN: length 37.9
  TOP w0.156: v1(48.76,55.55) 48.95,55.55 49.26,55.24 J30.126
  BOTTOM w0.156: R154.1 68.21,69.6 68.45,69.85 70.36,69.85 70.61,69.59 70.61,64.7 70.17,64.26 55.75,64.26 52.96,61.47 52.96,57.78 51.31,56.13 49.34,56.13 v1(48.76,55.55)
HDMI_TXCLKN_PORT: length 33.1
  TOP w0.124: U26.12 60.48,75.1 60.17,75.41 59.8,75.41 59.59,75.2 59.59,74.67 55.99,71.07 55.41,71.07 55.32,70.98 U28.1 U28.10 53.59,70.98 53.51,71.06 53.34,71.06 53.21,70.94 53.21,70.55 53.36,70.4 53.87,70.4 54.2,70.07 54.2,69.59 53.87,69.25 53.36,69.25 53.21,69.11 53.21,68.86 53.43,68.64 54.21,68.64 54.47,68.38 54.47,67.75 54.21,67.49 53.43,67.49 53.29,67.34 53.29,67.09 53.41,66.97 54.32,66.97 54.64,66.65 54.64,66.06 54.32,65.75 51.66,65.75 51.34,66.07 51.34,67.6 51.19,67.74 50.99,67.74 50.84,67.6 50.84,66.07 50.52,65.75 49.79,65.75 49.78,65.73 49.13,65.73 48.93,65.53 48.93,65.06 49.1,64.89 49.1,64.56 48.93,64.39 48.93,63.54 49.01,63.46 J30.127
HDMI_TXCLKP_PORT: length 33.6
  TOP w0.124: J30.129 48.51,63.46 48.6,63.54 48.6,65.67 48.99,66.06 49.64,66.06 49.66,66.07 50.38,66.07 50.52,66.21 50.52,67.73 50.85,68.07 51.33,68.07 51.67,67.73 51.67,66.21 51.8,66.07 54.18,66.07 54.31,66.2 54.31,66.51 54.18,66.64 53.28,66.64 52.96,66.95 52.96,67.48 53.3,67.81 54.08,67.81 54.14,67.88 54.14,68.24 54.08,68.31 53.3,68.31 52.89,68.72 52.89,69.24 53.22,69.58 53.73,69.58 53.88,69.73 53.88,69.93 53.73,70.08 53.22,70.08 52.89,70.41 52.89,71.07 53.2,71.39 53.5,71.39 53.59,71.48 U28.9 U28.2 55.32,71.48 55.41,71.4 55.85,71.4 59.26,74.8 59.26,75.34 59.69,75.77 60.1,75.77 60.59,76.26 U26.10
HDMI_TXDDC_SCL_PORT: length 26.5
  TOP w0.156: R158.2 79.33,67.27 Q10.3 77.09,67.18 76.2,66.29 69.57,66.29 D30.2 68.55,67.31 66.93,67.31 66.55,67.69 60.71,67.69 60.07,68.32 60.07,72.6 U26.15
HDMI_TXDDC_SDA_PORT: length 15.9
  TOP w0.156: R160.2 74.12,67.27 Q11.3 70.73,67.27 70.46,67.54 70.46,68.7 69.95,69.21 D29.2 68.55,69.85 65.53,69.85 62.59,72.79 U26.16
HDMITX_CEC_M0: length 51.5
  TOP w0.156: J30.128 48.76,51.08 v1(48.26,50.58) ; v1(81.09,68.29) 81.34,68.54 Q9.2
  BOTTOM w0.156: R156.2 81.67,68.87 v1(81.09,68.29) 81.09,67.24 80.78,66.93 73.38,66.93 73.03,66.57 73.03,63.24 72.64,62.86 56.77,62.86 54.86,60.96 54.86,57.15 51.31,53.59 49.84,53.59 49.53,53.28 49.53,51.85 v1(48.26,50.58)
HDMITX_SCL: length 44.7
  TOP w0.156: Q10.2 v1(76.14,68.16) ; v1(48.26,51.58) 47.76,52.08 J30.132
  BOTTOM w0.156: R157.2 76.72,68.74 v1(76.14,68.16) 75.54,67.56 72.65,67.56 72.36,67.28 72.36,63.93 71.81,63.37 56.39,63.37 54.23,61.21 54.23,57.28 51.05,54.1 49.21,54.1 48.9,53.79 48.9,52.22 v1(48.26,51.58)
HDMITX_SDA: length 38.5
  TOP w0.156: Q11.2 v1(71.18,68.16) ; J30.130 v1(48.26,52.58)
  BOTTOM w0.156: v1(48.26,52.58) 48.26,54.23 48.77,54.74 50.8,54.74 53.59,57.53 53.59,61.38 56.04,63.83 70.82,63.83 71.18,64.2 v1(71.18,68.16) 71.76,68.74 R159.2
HOST1_DM: length 7.3
  BOTTOM w0.158: R136.1 94.75,86.38 U19.7 U19.4 94.75,83.91 94.68,83.84 94.68,83.24 93.76,82.32 93.76,80.58 93.97,80.37 J15.2
HOST1_DP: length 7.4
  BOTTOM w0.158: J15.3 93.13,80.37 93.4,80.63 93.4,82.47 94.32,83.39 94.32,83.84 94.25,83.91 U19.5 U19.6 94.25,85.94 R137.1
HP_DET_L: length 131.5
  TOP w0.156: v1(48.92,24.94) 48.9,24.97 46.61,24.97 46.18,25.4 46.18,31.27 46.26,31.36 v1(46.26,51.58) ; v1(83.57,29.34) 86.5,29.34 86.82,29.65 86.82,50.34 84.99,52.17 80.04,52.17 79.76,52.44 J30.4
  ART03 w0.142: v1(48.92,24.94) 49.91,25.93 72.92,25.93 76.33,29.34 v1(83.57,29.34)
  BOTTOM w0.156: v1(46.26,51.58) 45.72,52.12 45.72,66.01 45.08,66.66 C187.1 R218.1
HP_SNS: length 69.4
  TOP w0.203: v1(21.51,50.58) 22.76,51.84 J30.224 ; J25.1 36.86,86.29 v1(36.86,82.73)
  ART03 w0.203: v1(27.45,71.13) 27.45,67.32 26.72,66.6 25.34,66.6 23.09,64.34 23.09,57.23 22.43,56.57 22.43,51.5 v1(21.51,50.58)
  BOTTOM w0.203: v1(36.86,82.73) 35.72,82.73 34.82,81.83 34.82,78.44 34.08,77.7 27.86,77.7 26.66,76.5 26.66,74.05 27.34,73.37 27.34,71.98 27.14,71.79 27.14,71.43 v1(27.45,71.13)
  BOTTOM w0.508: J25.1 37.31,86.75 R219.1 47.58,86.75 J26.1 53.9,86.67 R221.1
HPL_OUT: length 25.4
  TOP w0.203: v1(21.51,51.58) 22.26,52.34 J30.226 ; v1(26.51,67.12) 26.47,67.12 26.47,67.13 23.88,67.13 23.62,66.88 C189.1
  ART03 w0.203: v1(21.51,51.58) 22.07,52.15 22.07,56.72 22.73,57.38 22.73,64.49 25.37,67.12 v1(26.51,67.12)
HPR_OUT: length 30.4
  TOP w0.203: v1(27.97,67.13) 28,67.16 30.32,67.16 30.48,67 C190.1 ; J30.222 23.26,51.34 v1(21.51,49.58)
  ART03 w0.203: v1(27.97,67.13) 27.09,66.24 25.49,66.24 23.44,64.19 23.44,57.08 22.78,56.42 22.78,50.86 v1(21.51,49.58)
HUB_3V3: length 26.6
  TOP w0.305: R145.1 R146.1 121.41,87.49 120.98,87.06 120.98,83.35 121.41,82.92 v1(121.81,82.92) U22.20 ; U22.1 v1(123.59,79.14)
  BOTTOM w0.305: v1(123.59,79.14) 123.61,79.12 C130.1 124.47,80.2 124.16,80.51 122.05,80.51 121.81,80.74 v1(121.81,82.92) 122.59,83.69 C129.1 124.47,84.28 124.77,84.58 127.45,84.58 127.75,84.28 C128.1 127.75,82.71 R152.2
HUB_DM1: length 49.6
  TOP w0.158: v1(128.95,88.39) 128.83,88.27 128.83,83.53 128.28,82.99 127.76,82.99 127.69,82.92 U22.11
  ART04 w0.144: v1(128.95,88.39) 128.74,88.18 128.74,87.64 128.3,87.2 125.25,87.2 124.17,88.27 110.3,88.27 109.46,87.43 91.94,87.43 91.52,87.02 90.68,87.02 90.33,87.36 90.33,88.23 v1(90.17,88.39)
  BOTTOM w0.158: R130.2 v1(90.17,88.39)
HUB_DM2: length 29.7
  TOP w0.158: U22.9 127.69,81.92 127.76,81.99 128.79,81.99 v1(129.1,81.69)
  ART04 w0.144: v1(129.1,81.69) 129.1,81.28 128.81,80.99 127.38,80.99 127.09,81.28 127.09,81.8 arc(127.14,81.91) 127.25,81.95 arc(127.36,82) 127.41,82.11 127.41,82.37 arc(127.36,82.48) 127.25,82.53 arc(127.14,82.57) 127.09,82.68 127.09,82.95 arc(127.14,83.06) 127.25,83.1 arc(127.36,83.15) 127.41,83.26 127.41,83.52 arc(127.36,83.63) 127.25,83.68 arc(127.14,83.72) 127.09,83.83 127.09,84.23 126.4,84.93 123.96,84.93 122.17,86.71 120.42,86.71 119.48,85.77 118.88,85.77 arc(118.79,85.81) 118.76,85.9 arc(118.72,85.99) 118.63,86.03 118.31,86.03 arc(118.22,85.99) 118.18,85.9 arc(118.14,85.81) 118.05,85.77 117.73,85.77 arc(117.64,85.81) 117.61,85.9 arc(117.57,85.99) 117.48,86.03 117.16,86.03 arc(117.07,85.99) 117.03,85.9 arc(116.99,85.81) 116.9,85.77 116.58,85.77 arc(116.49,85.81) 116.45,85.9 arc(116.42,85.99) 116.33,86.03 116.01,86.03 arc(115.92,85.99) 115.88,85.9 arc(115.84,85.81) 115.75,85.77 115.43,85.77 arc(115.34,85.81) 115.3,85.9 arc(115.27,85.99) 115.18,86.03 114.86,86.03 arc(114.77,85.99) 114.73,85.9 arc(114.69,85.81) 114.6,85.77 114.28,85.77 arc(114.19,85.81) 114.15,85.9 arc(114.12,85.99) 114.03,86.03 113.71,86.03 arc(113.62,85.99) 113.58,85.9 arc(113.54,85.81) 113.45,85.77 112.57,85.77 111.6,86.74 111.6,87.49 111.75,87.63 v1(112.14,87.63)
  BOTTOM w0.158: R139.2 v1(112.14,87.63)
HUB_DM3: length 29.5
  TOP w0.158: v1(130.63,80.09) 130.43,80.29 129.21,80.29 128.51,80.99 127.76,80.99 127.69,80.92 U22.7
  ART04 w0.144: v1(130.63,80.09) 130.81,80.27 131.44,80.27 132.05,80.89 132.05,81.87 127.64,86.28 124.94,86.28 123.49,87.73 118.99,87.73 118.08,86.82 114.13,86.82 113.99,86.96 113.99,87.45 v1(114.17,87.63)
  BOTTOM w0.158: R132.2 v1(114.17,87.63)
HUB_DM4: length 52.1
  TOP w0.158: U22.5 125.59,79.32 125.66,79.25 125.66,78.59 126.25,78 127.27,78 127.64,77.63 127.64,74.68 126.47,73.52 126.47,72.9 123.81,70.24 121.16,70.24 118.36,67.43 118.36,65.86 117.99,65.49 108.34,65.49 107.51,64.66 107.51,64.05 arc(107.48,63.98) 107.4,63.95 107.4,63.95 arc(107.32,63.91) 107.29,63.84 107.29,63.42 arc(107.32,63.35) 107.4,63.31 107.4,63.31 arc(107.48,63.28) 107.51,63.21 107.51,62.79 arc(107.48,62.71) 107.4,62.68 107.4,62.68 arc(107.32,62.65) 107.29,62.57 107.29,62.16 arc(107.32,62.08) 107.4,62.05 107.4,62.05 arc(107.48,62.02) 107.51,61.94 107.51,61.52 arc(107.48,61.45) 107.4,61.41 107.4,61.41 arc(107.32,61.38) 107.29,61.31 107.29,60.89 arc(107.32,60.81) 107.4,60.78 107.4,60.78 arc(107.48,60.75) 107.51,60.67 107.51,60.26 arc(107.48,60.18) 107.4,60.15 107.4,60.15 arc(107.32,60.12) 107.29,60.04 107.29,59.62 arc(107.32,59.55) 107.4,59.52 107.4,59.52 arc(107.48,59.48) 107.51,59.41 107.51,58.99 arc(107.48,58.91) 107.4,58.88 107.4,58.88 arc(107.32,58.85) 107.29,58.77 107.29,58.36 arc(107.32,58.28) 107.4,58.25 107.4,58.25 arc(107.48,58.22) 107.51,58.14 107.51,57.12 106.83,56.44 98.81,56.44 98.61,56.64 98.61,57.39 98.93,57.71 R213.2
HUB_DP1: length 50.5
  TOP w0.158: U22.12 127.69,83.42 127.76,83.35 128.13,83.35 128.47,83.68 128.47,85.56 arc(128.4,85.72) 128.23,85.79 128.23,85.79 arc(128.06,85.86) 127.99,86.03 127.99,86.19 arc(128.06,86.36) 128.23,86.43 128.23,86.43 arc(128.4,86.5) 128.47,86.66 128.47,86.82 arc(128.4,86.99) 128.23,87.06 128.23,87.06 arc(128.06,87.13) 127.99,87.3 127.99,87.45 arc(128.06,87.62) 128.23,87.69 128.23,87.69 arc(128.4,87.76) 128.47,87.93 128.47,88.23 128.31,88.39 v1(127.99,88.39)
  ART04 w0.144: v1(127.99,88.39) 128.25,88.39 128.39,88.25 128.39,87.78 128.15,87.54 125.39,87.54 124.32,88.62 110.15,88.62 109.31,87.78 109.04,87.78 arc(108.94,87.82) 108.9,87.92 arc(108.86,88.02) 108.76,88.06 108.47,88.06 arc(108.37,88.02) 108.33,87.92 arc(108.29,87.82) 108.19,87.78 107.89,87.78 arc(107.79,87.82) 107.75,87.92 arc(107.71,88.02) 107.61,88.06 107.32,88.06 arc(107.22,88.02) 107.18,87.92 arc(107.14,87.82) 107.04,87.78 91.8,87.78 91.38,87.36 90.82,87.36 90.68,87.51 90.68,88.25 90.82,88.39 v1(91.19,88.39)
  BOTTOM w0.158: R131.2 v1(91.19,88.39)
HUB_DP2: length 29.5
  TOP w0.158: v1(129.1,82.65) 128.79,82.35 127.76,82.35 127.69,82.42 U22.10
  ART04 w0.144: v1(111.12,87.63) 111.26,87.5 111.26,86.6 112.43,85.43 119.63,85.43 120.57,86.37 122.03,86.37 123.82,84.58 126.26,84.58 126.75,84.09 126.75,81.14 127.24,80.64 128.95,80.64 129.57,81.27 129.57,82.17 v1(129.1,82.65)
  BOTTOM w0.158: R140.2 v1(111.12,87.63)
HUB_DP3: length 29.8
  TOP w0.158: v1(130.63,81.05) 130.63,80.81 130.47,80.65 129.36,80.65 128.66,81.35 127.76,81.35 127.69,81.42 U22.8
  ART04 w0.144: v1(113.16,87.63) 113.5,87.63 113.64,87.49 113.64,86.82 113.99,86.47 118.22,86.47 119.13,87.38 123.35,87.38 124.8,85.94 127.5,85.94 131.71,81.73 131.71,81.03 131.29,80.62 130.78,80.62 130.63,80.76 v1(130.63,81.05)
  BOTTOM w0.158: R133.2 v1(113.16,87.63)
HUB_DP4: length 52.1
  TOP w0.158: R214.2 97.92,57.71 98.24,57.39 98.24,56.49 98.66,56.08 106.98,56.08 107.87,56.97 107.87,64.51 108.49,65.12 118.14,65.12 118.72,65.71 118.72,67.28 121.31,69.87 123.96,69.87 126.84,72.75 126.84,73.37 128,74.53 128,77.78 127.42,78.36 126.4,78.36 126.02,78.74 126.02,79.25 126.09,79.32 U22.6
I2C0_SCL_PMIC: length 68.8
  TOP w0.156: J30.154 v1(40.26,52.58)
  ART03 w0.142: v1(43.08,73.38) 42.65,72.95 32.84,72.95 32.03,73.76 21.74,73.76 19.56,75.94 6.87,75.94 v1(5.28,77.53)
  BOTTOM w0.156: v1(5.28,77.53) 5.28,75.16 5.64,74.8 U12.6 ; v1(43.08,73.38) 43.08,60.27 40.26,57.46 v1(40.26,52.58)
I2C0_SDA_PMIC: length 72
  TOP w0.156: J30.152 40.76,52.08 v1(40.26,51.58)
  ART03 w0.142: v1(43.08,74.38) 42.36,73.66 33.15,73.66 32.51,74.29 22.1,74.29 19.81,76.58 7.23,76.58 v1(5.28,78.53)
  BOTTOM w0.156: v1(43.08,74.38) 43.56,73.89 43.56,59.97 40.82,57.23 40.82,52.14 v1(40.26,51.58) ; v1(5.28,78.53) 5.87,77.94 5.87,76.39 6.18,76.07 U12.5
